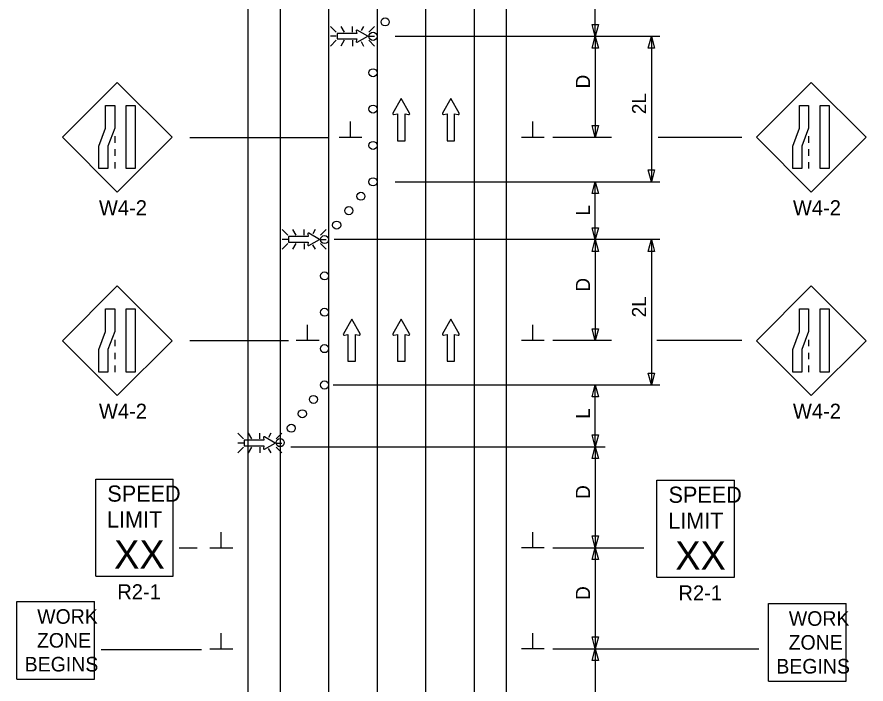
# Model space of a CAD drawing. Extents: x 16728 to 18479, y 5752 to 6927.
# Drawn here: x 16727.7 to 17148.1, y 6340.9 to 6671 of the extents above; entities that cross this region are included whole.
import ezdxf

# ---------------------------------------------------------------- set-up
doc = ezdxf.new("R2010")
doc.units = 0
for name, color, linetype in [('ALI_LEGAL_EX', 7, 'Continuous'), ('MT_SCRATCH_LEVEL_E', 7, 'Continuous'), ('PAVT_EDGE_EX', 7, 'Continuous'), ('TRAFFIC_SIGNS_PR', 7, 'Continuous'), ('TYPICAL_TEXT_DIMEN_PR', 7, 'Continuous')]:
    doc.layers.add(name, color=color, linetype=linetype)

msp = doc.modelspace()

# ---------------------------------------------------------------- linework, layer by layer
at = {"layer": 'ALI_LEGAL_EX'}
for p, q in [((16881.97, 6876.43), (16881.97, 5996.39)), ((16905.97, 6876.43), (16905.97, 5996.39)), ((16929.97, 6876.43), (16929.97, 5996.39))]:
    msp.add_line(p, q, dxfattribs=at)
for points in [[(16881.97, 6596.46), (16881.97, 6571.46)], [(16929.97, 6596.46), (16929.97, 6571.46)], [(16905.97, 6496.46), (16905.97, 6471.46)], [(16929.97, 6496.46), (16929.97, 6471.46)], [(16881.97, 6396.46), (16881.97, 6371.46)], [(16905.97, 6396.46), (16905.97, 6371.46)], [(16929.97, 6396.46), (16929.97, 6371.46)]]:
    msp.add_lwpolyline(points, dxfattribs=at)
at = {"layer": 'MT_SCRATCH_LEVEL_E'}
for p, q in [((16917.93, 6630.62), (16913.82, 6623.38)), ((16922.08, 6623.38), (16917.93, 6630.62)), ((16942.49, 6630.62), (16938.38, 6623.38)), ((16946.64, 6623.38), (16942.49, 6630.62)), ((16914.31, 6622.7), (16916.08, 6623.02)), ((16916.08, 6623.02), (16916.08, 6609.76)), ((16919.82, 6609.76), (16919.82, 6623.02)), ((16919.82, 6623.02), (16921.6, 6622.7)), ((16938.86, 6622.7), (16940.64, 6623.02)), ((16940.64, 6623.02), (16940.64, 6609.76)), ((16944.38, 6609.76), (16944.38, 6623.02)), ((16944.38, 6623.02), (16946.16, 6622.7)), ((16916.08, 6609.76), (16919.82, 6609.76)), ((16940.64, 6609.76), (16944.38, 6609.76)), ((16893.4, 6521.46), (16889.29, 6514.22)), ((16897.55, 6514.22), (16893.4, 6521.46)), ((16917.93, 6521.46), (16913.82, 6514.22)), ((16922.08, 6514.22), (16917.93, 6521.46)), ((16942.49, 6521.46), (16938.38, 6514.22)), ((16946.64, 6514.22), (16942.49, 6521.46)), ((16889.78, 6513.53), (16891.55, 6513.85)), ((16891.55, 6513.85), (16891.55, 6500.59)), ((16895.3, 6500.59), (16895.3, 6513.85)), ((16895.3, 6513.85), (16897.07, 6513.53)), ((16914.31, 6513.53), (16916.08, 6513.85)), ((16916.08, 6513.85), (16916.08, 6500.59)), ((16919.82, 6500.59), (16919.82, 6513.85)), ((16919.82, 6513.85), (16921.6, 6513.53)), ((16938.86, 6513.53), (16940.64, 6513.85)), ((16940.64, 6513.85), (16940.64, 6500.59)), ((16944.38, 6500.59), (16944.38, 6513.85)), ((16944.38, 6513.85), (16946.16, 6513.53)), ((16891.55, 6500.59), (16895.3, 6500.59)), ((16916.08, 6500.59), (16919.82, 6500.59)), ((16940.64, 6500.59), (16944.38, 6500.59))]:
    msp.add_line(p, q, dxfattribs=at)
for centre, start, end in [((16914.23, 6623.16), 150.4248, 279.9638), ((16921.67, 6623.16), 260.0362, 29.7731), ((16938.79, 6623.16), 150.4248, 279.9638), ((16946.23, 6623.16), 260.0362, 29.7731), ((16889.7, 6513.99), 150.4248, 279.9638), ((16897.14, 6513.99), 260.0362, 29.7731), ((16914.23, 6513.99), 150.4248, 279.9638), ((16921.67, 6513.99), 260.0362, 29.7731), ((16938.79, 6513.99), 150.4248, 279.9638), ((16946.23, 6513.99), 260.0362, 29.7731)]:
    msp.add_arc(centre, 0.463, start, end, dxfattribs=at)
at = {"layer": 'PAVT_EDGE_EX'}
for p, q in [((16841.97, 6926.69), (16841.97, 6016.42)), ((16857.97, 6926.69), (16857.97, 6016.42)), ((16953.97, 6926.69), (16953.97, 6016.42)), ((16969.97, 6926.69), (16969.97, 6016.42))]:
    msp.add_line(p, q, dxfattribs=at)
at = {"layer": 'TRAFFIC_SIGNS_PR'}
for p, q in [((16885.74, 6663.52), (16882.92, 6666.34)), ((16888.04, 6666.34), (16889.67, 6663.52)), ((16893.83, 6663.52), (16893.83, 6666.34)), ((16899.3, 6666.34), (16898.09, 6664.25)), ((16904.73, 6666.34), (16901.91, 6663.52)), ((16885.74, 6661.49), (16882.92, 6661.49)), ((16885.74, 6659.46), (16882.92, 6656.64)), ((16889.69, 6659.46), (16888.06, 6656.64)), ((16893.83, 6659.46), (16893.83, 6656.64)), ((16901.91, 6661.49), (16904.73, 6661.49)), ((16904.73, 6656.64), (16901.91, 6659.46)), ((16898.01, 6658.82), (16899.27, 6656.64)), ((16777.29, 6638.62), (16750.14, 6611.47)), ((16804.45, 6611.47), (16777.29, 6638.62)), ((17120.92, 6638.62), (17093.77, 6611.47)), ((17148.07, 6611.47), (17120.92, 6638.62)), ((16750.14, 6611.47), (16777.29, 6584.31)), ((16776.05, 6611.96), (16776.05, 6608.76)), ((16777.29, 6584.31), (16804.45, 6611.47)), ((17093.77, 6611.47), (17120.92, 6584.31)), ((17119.67, 6611.96), (17119.67, 6608.76)), ((17120.92, 6584.31), (17148.07, 6611.47)), ((16776.05, 6605.56), (16776.05, 6602.36)), ((17119.67, 6605.56), (17119.67, 6602.36)), ((16776.05, 6599.16), (16776.05, 6595.96)), ((17119.67, 6599.16), (17119.67, 6595.96)), ((16861.74, 6562.96), (16858.92, 6565.78)), ((16864.04, 6565.78), (16865.67, 6562.96)), ((16869.83, 6562.96), (16869.83, 6565.78)), ((16875.3, 6565.78), (16874.09, 6563.69)), ((16880.73, 6565.78), (16877.91, 6562.96)), ((16861.74, 6560.93), (16858.92, 6560.93)), ((16861.74, 6558.89), (16858.92, 6556.07)), ((16865.69, 6558.89), (16864.06, 6556.07)), ((16869.83, 6558.89), (16869.83, 6556.07)), ((16877.91, 6560.93), (16880.73, 6560.93)), ((16880.73, 6556.08), (16877.91, 6558.89)), ((16874.01, 6558.26), (16875.27, 6556.07)), ((16777.29, 6537.91), (16750.14, 6510.76)), ((16804.45, 6510.76), (16777.29, 6537.91)), ((17120.92, 6537.91), (17093.77, 6510.76)), ((17148.07, 6510.76), (17120.92, 6537.91)), ((16750.14, 6510.76), (16777.29, 6483.6)), ((16776.05, 6511.25), (16776.05, 6508.05)), ((16777.29, 6483.6), (16804.45, 6510.76)), ((17093.77, 6510.76), (17120.92, 6483.6)), ((17119.67, 6511.25), (17119.67, 6508.05)), ((17120.92, 6483.6), (17148.07, 6510.76)), ((16776.05, 6504.85), (16776.05, 6501.65)), ((17119.67, 6504.85), (17119.67, 6501.65)), ((16776.05, 6498.45), (16776.05, 6495.25)), ((17119.67, 6498.45), (17119.67, 6495.25)), ((16839.82, 6462.17), (16837, 6464.99)), ((16842.12, 6464.99), (16843.74, 6462.17)), ((16847.9, 6462.17), (16847.9, 6464.99)), ((16853.37, 6464.99), (16852.17, 6462.89)), ((16858.81, 6464.99), (16855.99, 6462.17)), ((16839.82, 6460.14), (16837, 6460.14)), ((16839.82, 6458.1), (16837, 6455.28)), ((16843.77, 6458.1), (16842.14, 6455.28)), ((16847.9, 6458.1), (16847.9, 6455.28)), ((16852.09, 6457.47), (16853.35, 6455.28)), ((16855.99, 6460.14), (16858.81, 6460.14)), ((16858.81, 6455.28), (16855.99, 6458.1)), ((16766.66, 6442.24), (16805.06, 6442.24)), ((16766.66, 6394.24), (16766.66, 6442.24)), ((16805.06, 6394.24), (16805.06, 6442.24)), ((17044.52, 6441.67), (17082.92, 6441.67)), ((17044.52, 6393.67), (17044.52, 6441.67)), ((17082.92, 6393.67), (17082.92, 6441.67)), ((16766.66, 6394.24), (16805.06, 6394.24)), ((17044.52, 6393.67), (17082.92, 6393.67)), ((16727.67, 6343.3), (16727.67, 6381.7)), ((16727.67, 6381.7), (16766.07, 6381.7)), ((16766.07, 6343.3), (16766.07, 6381.7)), ((17099.85, 6342.3), (17099.85, 6380.7)), ((17099.85, 6380.7), (17138.25, 6380.7)), ((17138.25, 6342.3), (17138.25, 6380.7)), ((16727.67, 6343.3), (16766.07, 6343.3)), ((17099.85, 6342.3), (17138.25, 6342.3))]:
    msp.add_line(p, q, dxfattribs=at)
for points in [[(16895.65, 6664.17), (16895.88, 6662.88), (16886.16, 6662.88), (16886.16, 6660.13), (16895.88, 6660.13), (16895.65, 6658.83)], [(16896.15, 6658.47), (16901.46, 6661.49), (16896.15, 6664.53)], [(16871.65, 6563.61), (16871.88, 6562.31), (16862.16, 6562.31), (16862.16, 6559.57), (16871.88, 6559.57), (16871.65, 6558.27)], [(16872.15, 6557.91), (16877.46, 6560.93), (16872.15, 6563.97)], [(16849.73, 6462.82), (16849.96, 6461.52), (16840.24, 6461.52), (16840.24, 6458.78), (16849.96, 6458.78), (16849.73, 6457.47)], [(16850.23, 6457.12), (16855.54, 6460.14), (16850.23, 6463.18)]]:
    msp.add_lwpolyline(points, dxfattribs=at)
for points in [[(16776.05, 6627.2), (16776.05, 6616.02), (16772.7, 6607.14), (16772.7, 6595.96), (16768.21, 6595.96), (16768.21, 6607.14), (16771.55, 6616.02), (16771.55, 6627.2)], [(16786.18, 6627.2), (16786.18, 6595.96), (16781.69, 6595.96), (16781.69, 6627.2)], [(17119.67, 6627.2), (17119.67, 6616.02), (17116.33, 6607.14), (17116.33, 6595.96), (17111.83, 6595.96), (17111.83, 6607.14), (17115.18, 6616.02), (17115.18, 6627.2)], [(17129.81, 6627.2), (17129.81, 6595.96), (17125.32, 6595.96), (17125.32, 6627.2)], [(16776.05, 6526.49), (16776.05, 6515.31), (16772.7, 6506.43), (16772.7, 6495.25), (16768.21, 6495.25), (16768.21, 6506.43), (16771.55, 6515.31), (16771.55, 6526.49)], [(16786.18, 6526.49), (16786.18, 6495.25), (16781.69, 6495.25), (16781.69, 6526.49)], [(17119.67, 6526.49), (17119.67, 6515.31), (17116.33, 6506.43), (17116.33, 6495.25), (17111.83, 6495.25), (17111.83, 6506.43), (17115.18, 6515.31), (17115.18, 6526.49)], [(17129.81, 6526.49), (17129.81, 6495.25), (17125.32, 6495.25), (17125.32, 6526.49)]]:
    msp.add_lwpolyline(points, close=True, dxfattribs=at)
for centre in [(16909.97, 6668.56), (16903.97, 6661.42), (16903.97, 6643.42), (16903.97, 6625.42), (16903.97, 6607.42), (16903.97, 6589.42), (16897.97, 6582.28), (16891.97, 6575.14), (16885.97, 6568), (16879.97, 6560.86), (16879.97, 6542.86), (16879.97, 6524.86), (16879.97, 6506.86), (16879.97, 6488.86), (16874.47, 6481.72), (16868.97, 6474.6), (16863.47, 6467.47), (16857.98, 6460.34)]:
    msp.add_circle(centre, 2, dxfattribs=at)
for centre, start, end in [((16895.99, 6664.23), 61.4833, 189.9593), ((16895.99, 6658.77), 170.7308, 298.8916), ((16871.99, 6563.67), 61.4833, 189.9593), ((16871.99, 6558.21), 170.7308, 298.8916), ((16850.07, 6462.88), 61.4833, 189.9593), ((16850.07, 6457.42), 170.7308, 298.8916)]:
    msp.add_arc(centre, 0.341, start, end, dxfattribs=at)
at = {"layer": 'TYPICAL_TEXT_DIMEN_PR'}
for p, q in [((17013.97, 6661.42), (17013.97, 6691.98)), ((17013.97, 6661.42), (17012.4, 6667.28)), ((17012.4, 6667.28), (17013.97, 6667.28)), ((17013.97, 6667.28), (17015.54, 6667.28)), ((17015.54, 6667.28), (17013.97, 6661.42)), ((17046.01, 6661.42), (16914.87, 6661.42)), ((17012.4, 6655.56), (17013.97, 6661.42)), ((17013.97, 6661.42), (17013.97, 6611.42)), ((17013.97, 6661.42), (17015.54, 6655.56)), ((17040.2, 6655.56), (17041.77, 6661.42)), ((17041.77, 6661.42), (17043.34, 6655.56)), ((17041.77, 6661.42), (17041.77, 6589.42)), ((17013.97, 6655.56), (17012.4, 6655.56)), ((17015.54, 6655.56), (17013.97, 6655.56)), ((17041.77, 6655.56), (17040.2, 6655.56)), ((17043.34, 6655.56), (17041.77, 6655.56)), ((16892.76, 6611.42), (16892.76, 6619.2)), ((16983.09, 6611.42), (16983.09, 6619.2)), ((17013.97, 6611.42), (17012.4, 6617.28)), ((17012.4, 6617.28), (17013.97, 6617.28)), ((17013.97, 6617.28), (17015.54, 6617.28)), ((17015.54, 6617.28), (17013.97, 6611.42)), ((17041.77, 6616.29), (17041.77, 6612.52)), ((16813.22, 6611.42), (16881.72, 6611.42)), ((16898.39, 6611.42), (16887.14, 6611.42)), ((16988.72, 6611.42), (16977.47, 6611.42)), ((17022.1, 6611.42), (16992.97, 6611.42)), ((17086.52, 6611.42), (17045.17, 6611.42)), ((17041.77, 6589.42), (17040.2, 6595.28)), ((17040.2, 6595.28), (17041.77, 6595.28)), ((17041.77, 6595.28), (17043.34, 6595.28)), ((17043.34, 6595.28), (17041.77, 6589.42)), ((16914.87, 6589.42), (17046.01, 6589.42)), ((17012.4, 6583.56), (17013.97, 6589.42)), ((17013.97, 6560.86), (17013.97, 6589.42)), ((17013.97, 6589.42), (17015.54, 6583.56)), ((17013.97, 6583.56), (17012.4, 6583.56)), ((17015.54, 6583.56), (17013.97, 6583.56)), ((17013.97, 6560.86), (17012.4, 6566.72)), ((17012.4, 6566.72), (17013.97, 6566.72)), ((17013.97, 6566.72), (17015.54, 6566.72)), ((17015.54, 6566.72), (17013.97, 6560.86)), ((17046.01, 6560.86), (16884.68, 6560.86)), ((17012.4, 6554.99), (17013.97, 6560.86)), ((17013.97, 6560.86), (17013.97, 6510.86)), ((17013.97, 6560.86), (17015.54, 6554.99)), ((17040.2, 6554.99), (17041.77, 6560.86)), ((17041.77, 6560.86), (17043.34, 6554.99)), ((17041.77, 6560.86), (17041.77, 6488.86)), ((17013.97, 6554.99), (17012.4, 6554.99)), ((17015.54, 6554.99), (17013.97, 6554.99)), ((17041.77, 6554.99), (17040.2, 6554.99)), ((17043.34, 6554.99), (17041.77, 6554.99)), ((16871.6, 6510.86), (16871.6, 6518.64)), ((16983.09, 6510.86), (16983.09, 6518.64)), ((17013.97, 6510.86), (17012.4, 6516.72)), ((17012.4, 6516.72), (17013.97, 6516.72)), ((17013.97, 6516.72), (17015.54, 6516.72)), ((17015.54, 6516.72), (17013.97, 6510.86)), ((17041.77, 6515.73), (17041.77, 6511.96)), ((16813.22, 6510.86), (16862.16, 6510.86)), ((16877.23, 6510.86), (16865.98, 6510.86)), ((16988.72, 6510.86), (16977.47, 6510.86)), ((17022.1, 6510.86), (16992.97, 6510.86)), ((17086.52, 6510.86), (17044.45, 6510.86)), ((17041.77, 6488.86), (17040.2, 6494.72)), ((17040.2, 6494.72), (17041.77, 6494.72)), ((17041.77, 6494.72), (17043.34, 6494.72)), ((17043.34, 6494.72), (17041.77, 6488.86)), ((16884.15, 6488.86), (17046.01, 6488.86)), ((16914.87, 6488.86), (17046.01, 6488.86)), ((17012.4, 6482.99), (17013.97, 6488.86)), ((17013.97, 6458.29), (17013.97, 6488.86)), ((17013.97, 6488.86), (17015.54, 6482.99)), ((17013.97, 6482.99), (17012.4, 6482.99)), ((17015.54, 6482.99), (17013.97, 6482.99)), ((17013.97, 6458.29), (17012.4, 6464.15)), ((17012.4, 6464.15), (17013.97, 6464.15)), ((17013.97, 6464.15), (17015.54, 6464.15)), ((17015.54, 6464.15), (17013.97, 6458.29)), ((16863.28, 6458.29), (17018.97, 6458.29)), ((17012.4, 6452.43), (17013.97, 6458.29)), ((17013.97, 6458.29), (17013.97, 6408.29)), ((17013.97, 6458.29), (17015.54, 6452.43)), ((17013.97, 6452.43), (17012.4, 6452.43)), ((17015.54, 6452.43), (17013.97, 6452.43)), ((16828.84, 6408.29), (16828.84, 6416.08)), ((16983.09, 6408.29), (16983.09, 6416.08)), ((17013.97, 6408.29), (17012.4, 6414.15)), ((17012.4, 6414.15), (17013.97, 6414.15)), ((17013.97, 6414.15), (17015.54, 6414.15)), ((17015.54, 6414.15), (17013.97, 6408.29)), ((16808.04, 6408.29), (16816.94, 6408.29)), ((16823.22, 6408.29), (16834.47, 6408.29)), ((16988.72, 6408.29), (16977.47, 6408.29)), ((16992.97, 6408.29), (17038.11, 6408.29)), ((17012.4, 6402.43), (17013.97, 6408.29)), ((17013.97, 6408.29), (17013.97, 6358.29)), ((17013.97, 6408.29), (17015.54, 6402.43)), ((17013.97, 6402.43), (17012.4, 6402.43)), ((17015.54, 6402.43), (17013.97, 6402.43)), ((16828.84, 6358.29), (16828.84, 6366.08)), ((16983.09, 6358.29), (16983.09, 6366.08)), ((17013.97, 6358.29), (17012.4, 6364.15)), ((17012.4, 6364.15), (17013.97, 6364.15)), ((17013.97, 6364.15), (17015.54, 6364.15)), ((17015.54, 6364.15), (17013.97, 6358.29)), ((16769.41, 6357.9), (16818.97, 6357.9)), ((16823.22, 6358.29), (16834.47, 6358.29)), ((16988.72, 6358.29), (16977.47, 6358.29)), ((16992.97, 6358.29), (17095.06, 6358.29)), ((17012.4, 6352.43), (17013.97, 6358.29)), ((17013.97, 6358.29), (17013.97, 6308.29)), ((17013.97, 6358.29), (17015.54, 6352.43)), ((17013.97, 6352.43), (17012.4, 6352.43)), ((17015.54, 6352.43), (17013.97, 6352.43))]:
    msp.add_line(p, q, dxfattribs=at)

# ---------------------------------------------------------------- texts
at = {"layer": 'TRAFFIC_SIGNS_PR'}
for s, height, p in [('W4-2', 7.44, (16768.25, 6572.87)), ('W4-2', 7.44, (17111.88, 6572.87)), ('W4-2', 7.44, (16768.25, 6472.16)), ('W4-2', 7.44, (17111.88, 6472.16)), ('SPEED', 8, (16772.42, 6431.11)), ('SPEED', 8, (17050.29, 6430.54)), ('LIMIT', 8, (16772.26, 6418.31)), ('LIMIT', 8, (17050.13, 6417.74)), ('XX', 14.031, (16775.77, 6398)), ('XX', 14.031, (17053.63, 6397.43)), ('R2-1', 7.44, (16777.33, 6382.8)), ('R2-1', 7.44, (17055.2, 6382.23)), ('WORK', 7.217, (16737.67, 6370.67)), ('WORK', 7.217, (17109.85, 6369.66)), ('ZONE', 7.217, (16737.55, 6358.86)), ('ZONE', 7.217, (17109.73, 6357.86)), ('BEGINS', 7.217, (16731.48, 6347.05)), ('BEGINS', 7.217, (17103.66, 6346.05))]:
    msp.add_text(s, height=height, dxfattribs=at).set_placement(p)
at = {"layer": 'TYPICAL_TEXT_DIMEN_PR'}
for s, p in [('D', (17011.41, 6635.64)), ('2L', (17039.21, 6622.92)), ('L', (17011.41, 6572.71)), ('D', (17011.41, 6535.07)), ('2L', (17039.21, 6522.36)), ('L', (17011.41, 6472.15)), ('D', (17011.41, 6432.51)), ('D', (17011.41, 6382.51))]:
    msp.add_text(s, height=7, rotation=90, dxfattribs=at).set_placement(p)

doc.saveas('drawing.dxf')
